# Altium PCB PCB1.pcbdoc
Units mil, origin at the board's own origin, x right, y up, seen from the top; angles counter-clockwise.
Board outline 750.3 x 1151.69 mil, 2 copper layers (Top Layer, Bottom Layer); 12 components, 11 nets, 36 pads, 9 vias.
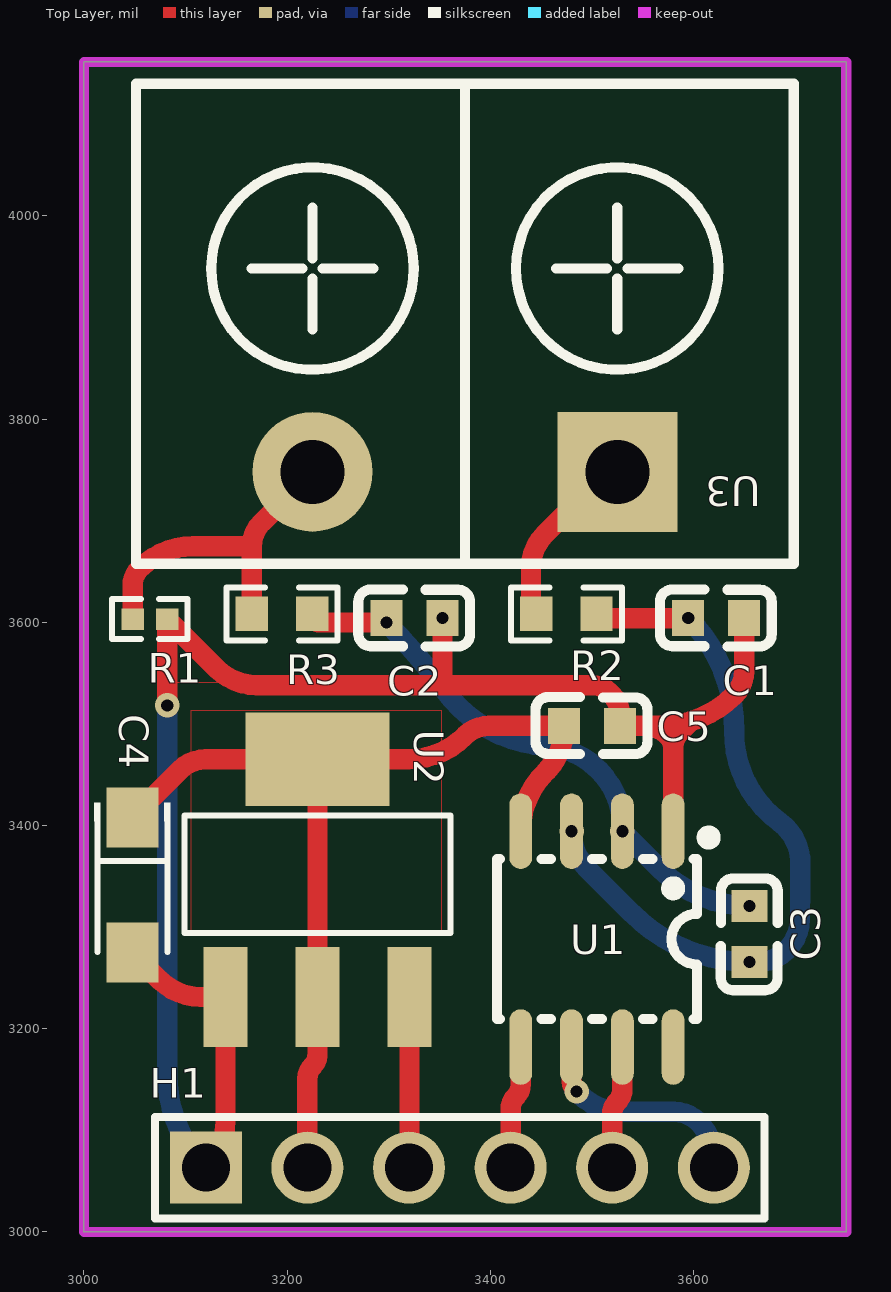
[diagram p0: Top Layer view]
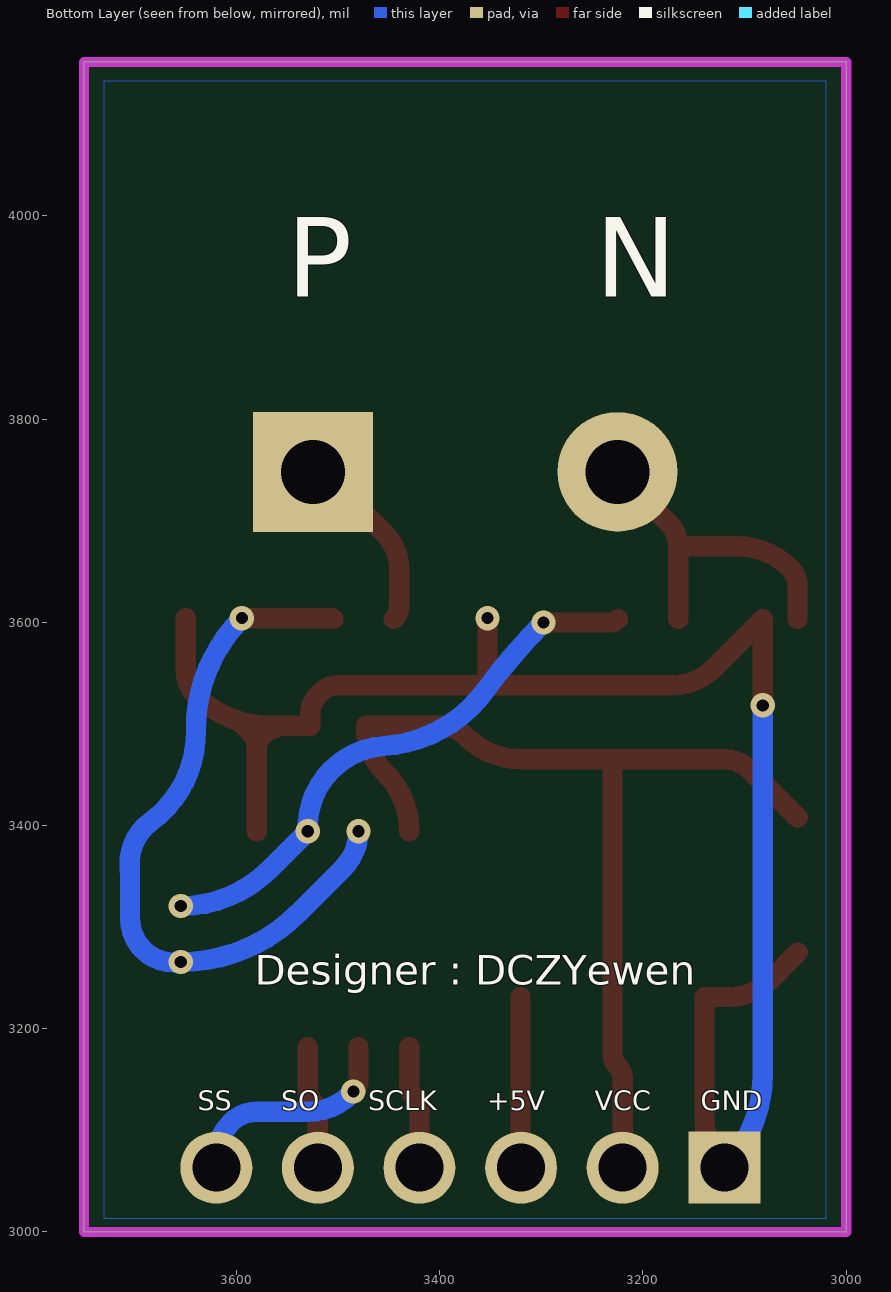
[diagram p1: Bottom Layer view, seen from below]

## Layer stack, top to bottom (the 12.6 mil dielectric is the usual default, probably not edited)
Top Layer: signal copper (thickness not stored)
Dielectric: dielectric 12.6, FR-4, Dk 4.8
Bottom Layer: signal copper (thickness not stored)

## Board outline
3000,3000 3000,4151.69 3750.3,4151.69 3750.3,3000

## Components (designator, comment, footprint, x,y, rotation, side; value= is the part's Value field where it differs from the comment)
C1 "CC0603KRX7R9BB224" C0603 3622.35,3604.22 r0 top
C2 "CC0603KRX7R9BB224" C0603 3325.46,3604.22 r0 top
C3 "CL10A225KO8NNNC" C0603 3655,3293.26 r90 top
C4 "CA45-A-16V-10uF-K" CAP-SMD_L3.2-W1.6-RD 3047.72,3341.49 r270 top
C5 "CC0603KRX7R9BB104" C0603 3500,3498.26 r0 top
H1 "2.54-1x6P直针" HDR-TH_6P-P2.54-V-M-1 3370,3063.26 r0 top
R1 "0402WGF1004TCE" R0402 3065,3603.26 r180 top
R2 "0603WAF7500T5E" R0603 3475,3608.38 r180 top
R3 "0603WAF7500T5E" R0603 3195,3608.38 r180 top
U1 "MAX31855KASA+T" SO-8_L4.9-W3.9-P1.27-LS5.9-BL 3505,3288.26 r180 top
U2 "AMS1117-3.3_C5250992" SOT-223-3_L6.5-W3.5-P3.05-LS7.0 3230,3348.26 r270 top
U3 "KF7.62-2P" CONN-TH_KF7.62-2P 3375,3748.26 r180 top

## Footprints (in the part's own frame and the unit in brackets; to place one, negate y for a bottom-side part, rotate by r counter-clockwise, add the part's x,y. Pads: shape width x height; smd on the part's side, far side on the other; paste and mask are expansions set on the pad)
C0603 [mm]
  rect 0.8x0.9 smd: 1(-0.7,0) 2(0.7,0)
  silkscreen extent -1.41,-0.71 1.39,0.72
CAP-SMD_L3.2-W1.6-RD [mm]
  rect 1.5x1.296 smd: 1(-1.686,0) 2(1.686,0)
  silkscreen extent -2.06,-0.95 1.68,0.95
CONN-TH_KF7.62-2P [mm]
  rect 3x3 hole 1.6: 1(-3.81,0)
  round 3 hole 1.6: 2(3.81,0)
  silkscreen extent -8.22,-9.7 8.22,2.3
HDR-TH_6P-P2.54-V-M-1 [mm]
  rect 1.8x1.8 hole 1.2: 1(-6.35,0)
  round 1.8 hole 1.2: 2(-3.81,0) 3(-1.27,0) 4(1.27,0) 5(3.81,0) 6(6.35,0)
  silkscreen extent -7.62,-1.27 7.62,1.27
R0402 [mm]
  rect 0.566x0.54 smd: 1(-0.433,0) 2(0.433,0)
  silkscreen extent -0.94,-0.5 0.94,0.5
R0603 [mil]
  rect 31.75x34.02 smd: 1(-29.66,0) 2(29.66,0)
  silkscreen extent -55,-26 55,26
SO-8_L4.9-W3.9-P1.27-LS5.9-BL [mil]
  oval 22.6x74.33 smd: 1(-75,-106.26) 2(-25,-106.26) 3(25,-106.26) 4(75,-106.26) 5(75,106.26) 6(25,106.26) 7(-25,106.26) 8(-75,106.26)
  silkscreen extent -116,-106 98,79
SOT-223-3_L6.5-W3.5-P3.05-LS7.0 [mm]
  rect 2.5x1.1 smd: 1(2.97,-2.3) 2(2.97,0) 3(2.97,2.3)
  rect 2.34x3.6 smd: 4(-2.97,0)
  silkscreen extent -1.57,-3.33 1.37,3.33

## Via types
v1: diameter 24.02, hole 12.01, Top Layer to Bottom Layer, 9 vias

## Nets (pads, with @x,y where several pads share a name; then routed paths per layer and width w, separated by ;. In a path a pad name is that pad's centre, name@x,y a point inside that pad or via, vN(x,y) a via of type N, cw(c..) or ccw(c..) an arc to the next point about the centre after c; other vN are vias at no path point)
+5V: H1.3 U2.3 | length 168.2
  Top Layer w20: H1.3 ccw(c3318.67,3064.59) 3320.55,3064.59 U2.3
GND: C1.2 C2.2 C4.2 C5.2 H1.1 R1.1 U1.1 U2.1 | length 1748.8
  Top Layer w20: C4.2 3074.86,3247.96 ccw(c3115,3288.09) 3115,3231.33 U2.1 3139.45,3110.22 cw(c3073.04,3110.22) H1.1 ; v1(3082.04,3518.26) R1.1 3130.8,3554.5 ccw(c3170,3593.69) 3170,3538.26 3350.51,3538.26 ; v1(3353.02,3604.22) 3353.02,3544.31 cw(c3344.46,3544.31) 3350.51,3538.26 ; U1.1 3580,3476.19 ; C1.2 3649.91,3552.19 cw(c3616.08,3552.19) 3640,3528.26 cw(c3567.57,3600.69) 3597.45,3502.72 ; 3350.51,3538.26 3500,3538.26 cw(c3500,3514.12) 3517.07,3531.19 3520,3528.26 cw(c3501.75,3510.01) 3527.56,3510.01 C5.2 3550.86,3498.26 ; 3550.86,3498.26 3567.57,3498.26 ccw(c3567.57,3600.69) 3597.45,3502.72 ; 3550.86,3498.26 cw(c3550.86,3464.12) 3575,3488.26 cw(c3562.93,3476.19) 3580,3476.19 ; 3580,3476.19 cw(c3601.92,3476.19) 3586.42,3491.69 3597.45,3502.72
  Bottom Layer w20: v1(3082.04,3518.26) 3082.04,3154.91 ccw(c3211.64,3154.91) H1.1
SCLK: H1.4 U1.5 | length 121.4
  Top Layer w20: H1.4 3420,3121.19 cw(c3437.07,3121.19) 3425,3133.26 ccw(c3412.93,3145.33) 3430,3145.33 U1.5
SO: H1.5 U1.7 | length 121.4
  Top Layer w20: H1.5 3520,3116.19 cw(c3537.07,3116.19) 3525,3128.26 ccw(c3512.93,3140.33) 3530,3140.33 U1.7
SS: H1.6 U1.6 | length 222.4
  Top Layer w20: U1.6 3480,3150.33 ccw(c3497.07,3150.33) v1(3485,3138.26)
  Bottom Layer w20: v1(3485,3138.26) 3487.32,3135.94 ccw(c3530,3178.62) 3530,3118.26 3580.86,3118.26 cw(c3580.86,3084.12) 3605,3108.26 cw(c3568.79,3072.05) 3620,3072.05 H1.6
TC_IN_N: C2.1 C3.2 R3.1 U1.2 | length 554.4
  Top Layer w20: R3.1@3224.66,3603.26 ccw(c3232.85,3611.46) 3232.85,3599.87 v1(3297.9,3599.87)
  Bottom Layer w20: v1(3297.9,3599.87) cw(c2893,3194.97) 3355,3533.26 ccw(c3464.04,3613.1) 3455,3478.26 cw(c3449.62,3397.99) v1(3530,3394.52) 3567.43,3357.1 ccw(c3655,3444.67) v1(3655,3320.82)
TC_IN_P: C1.1 C3.1 R2.1 U1.3 | length 725.4
  Top Layer w20: R2.1@3504.66,3603.26 cw(c3506.97,3600.95) 3506.97,3604.22 v1(3594.79,3604.22)
  Bottom Layer w20: v1(3480,3394.52) ccw(c3531.33,3394.52) 3495.03,3358.23 3539.87,3313.39 ccw(c3655,3428.52) v1(3655,3265.7) ccw(c3661.51,3308.52) 3704.82,3308.26 ccw(c-6294.14,3368.26) 3705,3368.26 ccw(c3655.78,3363.35) 3685,3403.26 cw(c3749.96,3491.99) 3640,3493.26 ccw(c3485.62,3495.05) v1(3594.79,3604.22)
TC_N: R1.2 R3.2 U3.2 | length 338.2
  Top Layer w20: R1.2 3047.96,3636.27 cw(c3072,3636.27) 3055,3653.26 cw(c3107.34,3600.93) 3107.34,3674.94 3165.34,3674.94 ; R3.2@3165.34,3603.26 3165.34,3674.94 ; U3.2@3220,3753.26 cw(c3195.86,3753.26) 3212.93,3736.19 3175,3698.26 ccw(c3198.32,3674.94) 3165.34,3674.94
TC_P: R2.2 U3.1 | length 182.5
  Top Layer w20: R2.2@3445.34,3603.26 cw(c3458.23,3616.16) 3440,3616.16 3440,3653.26 cw(c3488.28,3653.26) 3454.14,3687.41 U3.1@3520,3753.26
VCC: C4.1 C5.1 H1.2 U1.4 U2.2 U2.4 | length 975.6
  Top Layer w20: C4.1 3094.45,3454.61 cw(c3120,3429.06) 3120,3465.19 U2.4 ; H1.2 3220,3151.19 cw(c3237.07,3151.19) 3225,3163.26 ccw(c3212.93,3175.33) 3230,3175.33 U2.2 U2.4 ; U1.4 cw(c3511.46,3394.52) 3453.86,3452.12 3455,3453.26 ccw(c3412.9,3495.37) 3472.44,3495.37 C5.1 3399.14,3498.26 ccw(c3399.14,3464.12) 3375,3488.26 cw(c3319.3,3543.96) 3319.3,3465.19 U2.4
"": U1.8

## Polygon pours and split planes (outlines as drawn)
VCC on Top Layer (solid, remove dead copper, pour order 0): 3105,3294.27 3352.2,3294.27 3352.2,3513.26 3105,3513.26
GND on Bottom Layer (solid, remove dead copper, pour order 2): 3020,3013.26 3730,3013.26 3730,4133.26 3020,4133.26
GND on Top Layer (solid, remove dead copper, pour order 1): 3154.04,3540.61 3085.55,3540.61 cw(c3085.55,3545.57) 3082.04,3542.06 3082.04,3603.26 3138.08,3547.22 ccw(c3154.04,3563.17)

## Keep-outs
Board Outline Layer:
  the board outline again, w10

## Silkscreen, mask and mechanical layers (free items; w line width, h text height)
Bottom Silkscreen Layer:
  text "N" at 3246.88,3920.29 h78.45
  text "P" at 3550.76,3920.29 h78.45
  text "Designer : DCZYewen" at 3581.99,3243.25 h29.2
  text "GND" at 3143.34,3119.92 h19.47
  text "VCC" at 3247.3,3119.92 h19.47
  text "+5V" at 3353.17,3119.92 h19.47
  text "SCLK" at 3470.48,3119.92 h19.47
  text "SO" at 3556.06,3119.92 h19.47
  text "SS" at 3638.22,3119.92 h19.47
